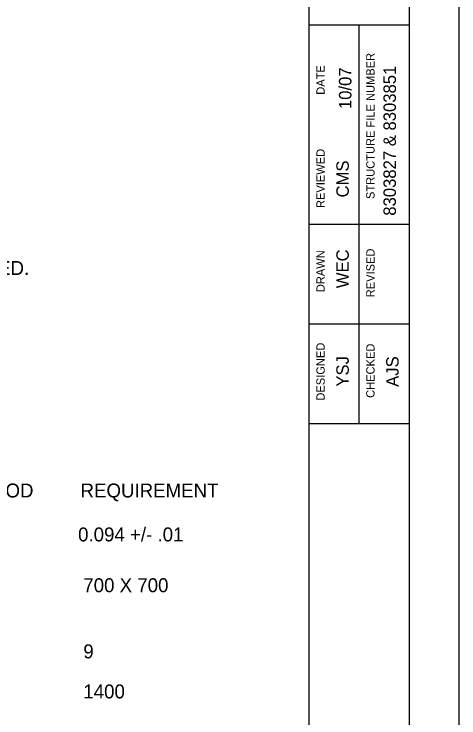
# Model space of a CAD drawing. Extents: x 0 to 34, y 0 to 22.
# Drawn here: x 29.54 to 34, y 11.04 to 18.11 of the extents above; entities that cross this region are included whole.
import ezdxf

# ---------------------------------------------------------------- set-up
doc = ezdxf.new("R2010")
doc.units = 0
for name, color, linetype in [('SH_Border', 7, 'Continuous'), ('SH_Cut_Line', 7, 'Continuous'), ('SH_Data', 7, 'Continuous'), ('SH_Text', 7, 'Continuous')]:
    doc.layers.add(name, color=color, linetype=linetype)

msp = doc.modelspace()

# ---------------------------------------------------------------- linework, layer by layer
at = {"layer": 'SH_Border'}
for p, q in [((32.5, 0.5), (32.5, 21.5)), ((32.5, 0.5), (32.5, 21.5)), ((32.5, 0.5), (32.5, 21.5)), ((32.5, 18), (33.5, 18)), ((32.5, 18), (33.5, 18)), ((32.5, 18), (33.5, 18)), ((33, 14), (33, 18)), ((33, 14), (33, 18)), ((33, 14), (33, 18)), ((32.5, 16), (33.5, 16)), ((32.5, 16), (33.5, 16)), ((32.5, 16), (33.5, 16)), ((32.5, 15), (33.5, 15)), ((32.5, 15), (33.5, 15)), ((32.5, 15), (33.5, 15)), ((32.5, 14), (33.5, 14)), ((32.5, 14), (33.5, 14)), ((32.5, 14), (33.5, 14))]:
    msp.add_line(p, q, dxfattribs=at)
msp.add_lwpolyline([(2, 21.5), (33.5, 21.5), (33.5, 0.5), (2, 0.5)], close=True, dxfattribs=at)
at = {"layer": 'SH_Cut_Line'}
msp.add_lwpolyline([(0, 22), (34, 22), (34, 0), (0, 0)], close=True, dxfattribs=at)

# ---------------------------------------------------------------- texts
at = {"layer": 'SH_Data'}
for s, height, p in [('STRUCTURE FILE NUMBER', 0.0833, (33.1542, 16.253)), ('DATE', 0.0833, (32.6542, 17.2997)), ('10/07', 0.125, (32.9221, 17.1558)), ('8303827 & 8303851', 0.125, (33.3684, 16.0856)), ('REVIEWED', 0.0833, (32.6542, 16.1627)), ('CMS', 0.125, (32.8958, 16.2687)), ('DRAWN', 0.0833, (32.6542, 15.3177)), ('WEC', 0.125, (32.8958, 15.3576)), ('REVISED', 0.0833, (33.1542, 15.2665)), ('DESIGNED', 0.0833, (32.6542, 14.2292)), ('CHECKED', 0.0833, (33.1542, 14.2567)), ('YSJ', 0.125, (32.8958, 14.3699)), ('AJS', 0.125, (33.3958, 14.3675))]:
    msp.add_text(s, height=height, rotation=90, dxfattribs=at).set_placement(p)
at = {"layer": 'SH_Text'}
for s, p in [('LENGTH, OR 6 INCHES IN LENGTH IF THE LAP IS VULCANIZED OR ADHESIVE BONDED.', (21.8267, 15.4905)), ('ASTM METHOD', (28.3507, 13.2569)), ('REQUIREMENT', (30.2058, 13.2569)), ('0.094 +/- .01', (30.1813, 12.8159)), ('700 X 700', (30.2337, 12.3059)), ('9', (30.2337, 11.6419)), ('1400', (30.2337, 11.2399))]:
    msp.add_text(s, height=0.14, dxfattribs=at).set_placement(p)

doc.saveas('drawing.dxf')
